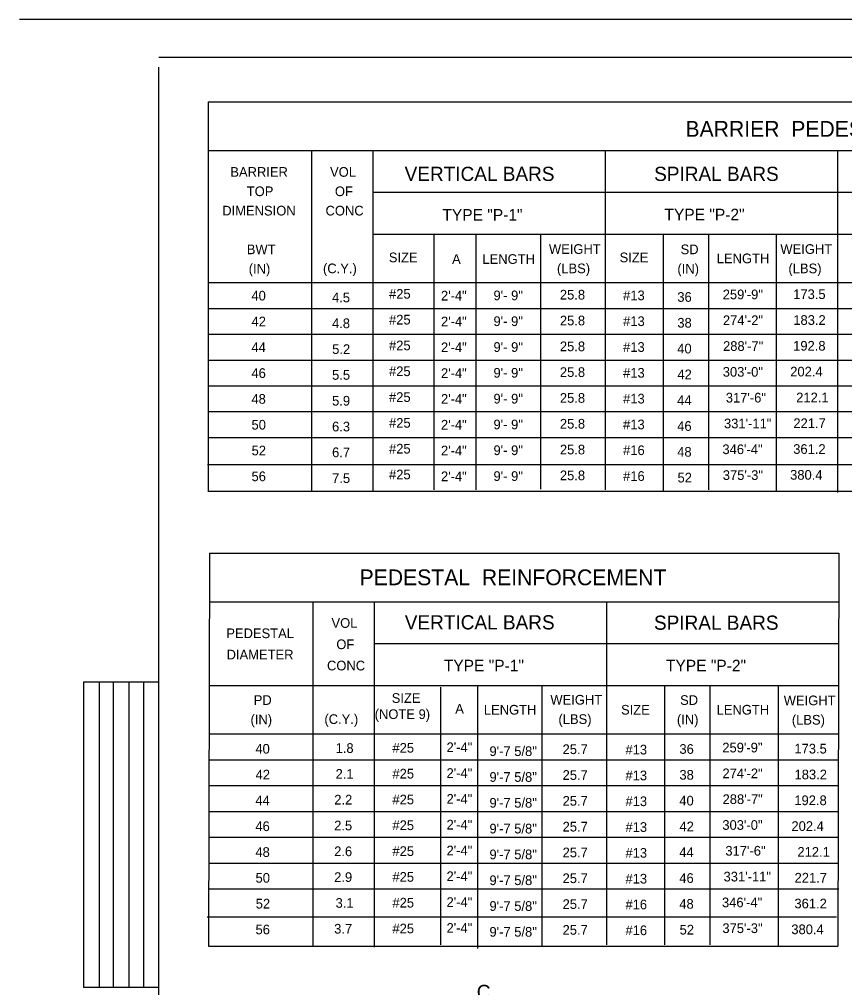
# Model space of a CAD drawing. Extents: x -3 to 26050223, y 0 to 12035012.
# Drawn here: x 0 to 21.31, y 18.31 to 43.33 of the extents above; entities that cross this region are included whole.
import ezdxf

# ---------------------------------------------------------------- set-up
doc = ezdxf.new("R2010")
doc.units = 0
for name, color, linetype in [('1', 7, 'Continuous'), ('2', 7, 'Continuous'), ('39', 7, 'Continuous')]:
    doc.layers.add(name, color=color, linetype=linetype)

msp = doc.modelspace()

# ---------------------------------------------------------------- linework, layer by layer
at = {"layer": '1'}
for p, q in [((68.892, 43.325), (0, 43.325)), ((68.183, 42.342), (3.6, 42.342)), ((3.6, 0.762), (3.6, 42.087)), ((1.667, 18.317), (1.667, 26.217)), ((1.667, 26.217), (3.6, 26.217)), ((2.067, 18.317), (2.067, 26.217)), ((2.433, 18.317), (2.433, 26.217)), ((2.833, 18.317), (2.833, 26.217)), ((3.217, 18.317), (3.217, 26.217)), ((3.6, 18.317), (1.667, 18.317))]:
    msp.add_line(p, q, dxfattribs=at)
at = {"layer": '39'}
for p, q in [((4.871, 41.192), (41.454, 41.192)), ((4.871, 41.192), (4.871, 31.124)), ((4.871, 39.942), (41.454, 39.942)), ((7.538, 39.942), (7.538, 31.14)), ((9.121, 39.942), (9.121, 31.14)), ((15.121, 39.942), (15.121, 31.173)), ((21.121, 39.942), (21.121, 31.107)), ((9.121, 38.859), (41.454, 38.859)), ((9.121, 37.776), (39.788, 37.776)), ((10.704, 37.776), (10.704, 31.173)), ((11.788, 37.776), (11.788, 31.173)), ((13.454, 37.776), (13.454, 31.189)), ((16.621, 37.776), (16.621, 31.14)), ((17.788, 37.776), (17.788, 31.173)), ((19.538, 37.776), (19.538, 31.156)), ((4.871, 36.526), (41.454, 36.526)), ((4.871, 35.859), (41.454, 35.859)), ((4.871, 35.192), (41.454, 35.192)), ((4.871, 34.526), (41.454, 34.526)), ((4.871, 33.859), (41.454, 33.859)), ((4.871, 33.192), (41.454, 33.192)), ((4.871, 32.526), (41.454, 32.526)), ((4.859, 31.831), (41.442, 31.831)), ((4.898, 31.137), (41.482, 31.137)), ((4.908, 29.533), (4.88, 19.381)), ((4.908, 29.533), (21.158, 29.533)), ((21.158, 29.533), (21.13, 19.381)), ((4.908, 28.283), (21.158, 28.283)), ((7.575, 28.283), (7.575, 19.376)), ((9.158, 28.283), (9.158, 19.362)), ((15.158, 28.283), (15.158, 19.417)), ((9.158, 27.2), (21.158, 27.2)), ((4.908, 26.117), (21.158, 26.117)), ((10.874, 26.079), (10.874, 19.417)), ((11.825, 26.117), (11.825, 19.321)), ((13.492, 26.117), (13.492, 19.403)), ((16.658, 26.117), (16.658, 19.417)), ((17.825, 26.117), (17.825, 19.417)), ((19.592, 26.117), (19.592, 19.376)), ((4.908, 24.867), (21.158, 24.867)), ((4.908, 24.2), (21.158, 24.2)), ((4.908, 23.533), (21.158, 23.533)), ((4.908, 22.867), (21.158, 22.867)), ((4.908, 22.2), (21.158, 22.2)), ((4.908, 21.533), (21.158, 21.533)), ((4.908, 20.867), (21.158, 20.867)), ((4.844, 20.139), (21.094, 20.139)), ((4.88, 19.381), (21.13, 19.381))]:
    msp.add_line(p, q, dxfattribs=at)

# ---------------------------------------------------------------- texts
at = {"layer": '2'}
for s, height, p in [('VERTICAL BARS', 0.36665, (9.946, 39.151)), ('SPIRAL BARS', 0.36665, (16.388, 39.151)), ('BARRIER', 0.25, (5.446, 39.259)), ('VOL', 0.25, (8.021, 39.259)), ('TOP', 0.25, (5.871, 38.759)), ('OF', 0.25, (8.146, 38.759)), ('DIMENSION', 0.25, (5.238, 38.259)), ('CONC', 0.25, (7.904, 38.259)), ('TYPE "P-1"', 0.3, (10.921, 38.126)), ('TYPE "P-2"', 0.3, (16.654, 38.134)), ('WEIGHT', 0.25, (13.671, 37.267)), ('WEIGHT', 0.25, (19.646, 37.267)), ('BWT', 0.25, (5.871, 37.259)), ('SIZE', 0.25, (9.538, 37.051)), ('SIZE', 0.25, (15.496, 37.051)), ('SD', 0.25, (17.071, 37.259)), ('LENGTH', 0.25, (18.004, 37.026)), ('(IN)', 0.25, (5.921, 36.759)), ('(C.Y.)', 0.25, (7.838, 36.767)), ('A', 0.25, (11.171, 37.009)), ('LENGTH', 0.25, (11.954, 37.009)), ('(LBS)', 0.25, (13.879, 36.767)), ('(IN)', 0.25, (16.988, 36.759)), ('(LBS)', 0.25, (19.854, 36.767)), ('40', 0.25, (5.991, 36.063)), ('#25', 0.25, (9.543, 36.11)), ('2\'-4"', 0.25, (10.884, 36.063)), ('9\'- 9"', 0.25, (12.24, 36.07)), ('25.8', 0.25, (13.954, 36.088)), ('#13', 0.25, (15.586, 36.07)), ('36', 0.25, (16.986, 36.029)), ('259\'-9"', 0.25, (18.158, 36.095)), ('173.5', 0.25, (19.977, 36.101)), ('4.5', 0.25, (8.071, 36.016)), ('42', 0.25, (5.993, 35.396)), ('4.8', 0.25, (8.071, 35.349)), ('#25', 0.25, (9.543, 35.443)), ('2\'-4"', 0.25, (10.884, 35.396)), ('9\'- 9"', 0.25, (12.24, 35.403)), ('25.8', 0.25, (13.954, 35.421)), ('#13', 0.25, (15.586, 35.403)), ('38', 0.25, (16.986, 35.363)), ('274\'-2"', 0.25, (18.162, 35.428)), ('183.2', 0.25, (19.98, 35.434)), ('#25', 0.25, (9.543, 34.777)), ('288\'-7"', 0.25, (18.166, 34.762)), ('192.8', 0.25, (19.976, 34.768)), ('44', 0.25, (5.991, 34.729)), ('5.2', 0.25, (8.075, 34.682)), ('2\'-4"', 0.25, (10.884, 34.729)), ('9\'- 9"', 0.25, (12.24, 34.736)), ('25.8', 0.25, (13.954, 34.754)), ('#13', 0.25, (15.586, 34.736)), ('40', 0.25, (16.983, 34.696)), ('46', 0.25, (5.991, 34.063)), ('5.5', 0.25, (8.073, 34.016)), ('#25', 0.25, (9.543, 34.11)), ('2\'-4"', 0.25, (10.884, 34.063)), ('9\'- 9"', 0.25, (12.24, 34.07)), ('25.8', 0.25, (13.954, 34.088)), ('#13', 0.25, (15.586, 34.07)), ('42', 0.25, (16.988, 34.029)), ('303\'-0"', 0.25, (18.159, 34.095)), ('202.4', 0.25, (19.901, 34.101)), ('48', 0.25, (5.991, 33.396)), ('5.9', 0.25, (8.073, 33.349)), ('#25', 0.25, (9.543, 33.443)), ('2\'-4"', 0.25, (10.884, 33.396)), ('9\'- 9"', 0.25, (12.24, 33.403)), ('25.8', 0.25, (13.954, 33.421)), ('#13', 0.25, (15.586, 33.403)), ('44', 0.25, (16.982, 33.363)), ('317\'-6"', 0.25, (18.237, 33.428)), ('212.1', 0.25, (20.055, 33.434)), ('#25', 0.25, (9.543, 32.777)), ('331\'-11"', 0.25, (18.191, 32.762)), ('221.7', 0.25, (19.982, 32.768)), ('50', 0.25, (5.993, 32.729)), ('6.3', 0.25, (8.072, 32.682)), ('2\'-4"', 0.25, (10.884, 32.729)), ('9\'- 9"', 0.25, (12.24, 32.736)), ('25.8', 0.25, (13.954, 32.754)), ('#13', 0.25, (15.586, 32.736)), ('46', 0.25, (16.983, 32.696)), ('52', 0.25, (5.995, 32.063)), ('6.7', 0.25, (8.073, 32.016)), ('#25', 0.25, (9.543, 32.11)), ('2\'-4"', 0.25, (10.884, 32.063)), ('9\'- 9"', 0.25, (12.24, 32.07)), ('25.8', 0.25, (13.954, 32.088)), ('#16', 0.25, (15.586, 32.07)), ('48', 0.25, (16.983, 32.029)), ('346\'-4"', 0.25, (18.15, 32.095)), ('361.2', 0.25, (19.978, 32.101)), ('56', 0.25, (5.993, 31.396)), ('7.5', 0.25, (8.074, 31.349)), ('#25', 0.25, (9.543, 31.443)), ('2\'-4"', 0.25, (10.884, 31.396)), ('9\'- 9"', 0.25, (12.24, 31.403)), ('25.8', 0.25, (13.954, 31.421)), ('#16', 0.25, (15.586, 31.403)), ('52', 0.25, (16.991, 31.363)), ('375\'-3"', 0.25, (18.16, 31.428)), ('380.4', 0.25, (19.898, 31.434)), ('VOL', 0.25, (8.058, 27.608)), ('VERTICAL BARS', 0.36665, (9.95, 27.567)), ('SPIRAL BARS', 0.36665, (16.383, 27.558)), ('PEDESTAL', 0.25, (5.342, 27.342)), ('OF', 0.25, (8.183, 27.058)), ('DIAMETER', 0.25, (5.35, 26.792)), ('CONC', 0.25, (7.942, 26.508)), ('TYPE "P-1"', 0.3, (10.958, 26.483)), ('TYPE "P-2"', 0.3, (16.692, 26.483)), ('PD', 0.25, (6.05, 25.617)), ('SIZE', 0.25, (9.613, 25.669)), ('WEIGHT', 0.25, (13.708, 25.625)), ('SD', 0.25, (17.058, 25.617)), ('WEIGHT', 0.25, (19.733, 25.608)), ('(NOTE 9)', 0.25, (9.173, 25.253)), ('A', 0.25, (11.253, 25.392)), ('LENGTH', 0.25, (11.992, 25.367)), ('SIZE', 0.25, (15.533, 25.367)), ('LENGTH', 0.25, (18, 25.367)), ('(IN)', 0.25, (5.967, 25.117)), ('(C.Y.)', 0.25, (7.875, 25.125)), ('(LBS)', 0.25, (13.917, 25.125)), ('(IN)', 0.25, (16.975, 25.117)), ('(LBS)', 0.25, (19.942, 25.108)), ('40', 0.25, (6.093, 24.358)), ('1.8', 0.25, (8.164, 24.377)), ('#25', 0.25, (9.631, 24.383)), ('2\'-4"', 0.25, (11.028, 24.398)), ('9\'-7 5/8"', 0.25, (12.136, 24.297)), ('25.7', 0.25, (14.024, 24.347)), ('#13', 0.25, (15.647, 24.337)), ('36', 0.25, (17.04, 24.353)), ('259\'-9"', 0.25, (18.147, 24.39)), ('173.5', 0.25, (20.008, 24.362)), ('42', 0.25, (6.098, 23.691)), ('2.1', 0.25, (8.164, 23.71)), ('#25', 0.25, (9.631, 23.716)), ('2\'-4"', 0.25, (11.028, 23.731)), ('9\'-7 5/8"', 0.25, (12.136, 23.63)), ('25.7', 0.25, (14.024, 23.681)), ('#13', 0.25, (15.647, 23.67)), ('38', 0.25, (17.04, 23.686)), ('274\'-2"', 0.25, (18.151, 23.724)), ('183.2', 0.25, (20.012, 23.695)), ('44', 0.25, (6.093, 23.025)), ('2.2', 0.25, (8.129, 23.044)), ('#25', 0.25, (9.631, 23.049)), ('2\'-4"', 0.25, (11.028, 23.065)), ('25.7', 0.25, (14.024, 23.014)), ('40', 0.25, (17.037, 23.019)), ('288\'-7"', 0.25, (18.154, 23.057)), ('192.8', 0.25, (20.007, 23.028)), ('9\'-7 5/8"', 0.25, (12.136, 22.963)), ('#13', 0.25, (15.647, 23.003)), ('46', 0.25, (6.093, 22.358)), ('2.5', 0.25, (8.127, 22.377)), ('#25', 0.25, (9.631, 22.383)), ('2\'-4"', 0.25, (11.028, 22.398)), ('9\'-7 5/8"', 0.25, (12.136, 22.297)), ('25.7', 0.25, (14.024, 22.347)), ('#13', 0.25, (15.647, 22.337)), ('42', 0.25, (17.041, 22.353)), ('303\'-0"', 0.25, (18.148, 22.39)), ('202.4', 0.25, (19.932, 22.362)), ('48', 0.25, (6.093, 21.691)), ('2.6', 0.25, (8.127, 21.71)), ('#25', 0.25, (9.631, 21.716)), ('2\'-4"', 0.25, (11.028, 21.731)), ('9\'-7 5/8"', 0.25, (12.136, 21.63)), ('25.7', 0.25, (14.024, 21.681)), ('#13', 0.25, (15.647, 21.67)), ('44', 0.25, (17.036, 21.686)), ('317\'-6"', 0.25, (18.226, 21.724)), ('212.1', 0.25, (20.086, 21.695)), ('50', 0.25, (6.097, 21.025)), ('2.9', 0.25, (8.127, 21.044)), ('#25', 0.25, (9.631, 21.049)), ('2\'-4"', 0.25, (11.028, 21.065)), ('25.7', 0.25, (14.024, 21.014)), ('46', 0.25, (17.037, 21.019)), ('331\'-11"', 0.25, (18.179, 21.057)), ('221.7', 0.25, (20.013, 21.028)), ('9\'-7 5/8"', 0.25, (12.136, 20.963)), ('#13', 0.25, (15.647, 21.003)), ('52', 0.25, (6.102, 20.358)), ('3.1', 0.25, (8.163, 20.377)), ('#25', 0.25, (9.631, 20.383)), ('2\'-4"', 0.25, (11.028, 20.398)), ('9\'-7 5/8"', 0.25, (12.136, 20.297)), ('25.7', 0.25, (14.024, 20.347)), ('#16', 0.25, (15.647, 20.337)), ('48', 0.25, (17.037, 20.353)), ('346\'-4"', 0.25, (18.139, 20.39)), ('361.2', 0.25, (20.009, 20.362)), ('56', 0.25, (6.097, 19.691)), ('3.7', 0.25, (8.127, 19.71)), ('#25', 0.25, (9.631, 19.716)), ('2\'-4"', 0.25, (11.028, 19.731)), ('9\'-7 5/8"', 0.25, (12.136, 19.63)), ('25.7', 0.25, (14.024, 19.681)), ('#16', 0.25, (15.647, 19.67)), ('52', 0.25, (17.045, 19.686)), ('375\'-3"', 0.25, (18.149, 19.724)), ('380.4', 0.25, (19.929, 19.695)), ('C', 0.367, (11.808, 18.02))]:
    msp.add_text(s, height=height, dxfattribs=at).set_placement(p)
at = {"layer": '39'}
for s, p in [('BARRIER  PEDESTAL  REINFORCEMENT', (17.196, 40.292)), ('PEDESTAL  REINFORCEMENT', (8.783, 28.708))]:
    msp.add_text(s, height=0.40835, dxfattribs=at).set_placement(p)

doc.saveas('drawing.dxf')
